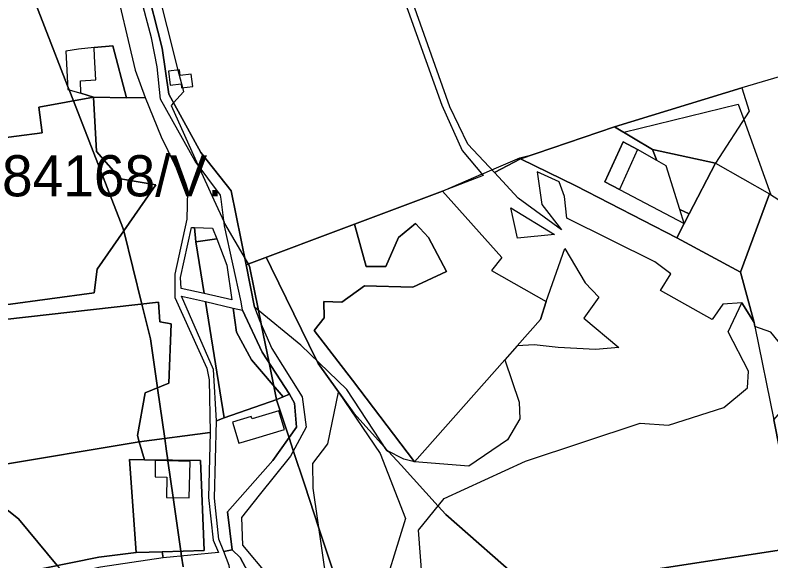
# Model space of a CAD drawing. Extents: x -477304 to -465429, y -1159113 to -1149210.
# Drawn here: x -475362.8 to -475087.6, y -1151434.9 to -1151236.1 of the extents above; entities that cross this region are included whole.
import ezdxf

# ---------------------------------------------------------------- set-up
doc = ezdxf.new("R2010")
doc.units = 0
for name, color, linetype in [('BPEJ_s', 7, 'Continuous'), ('orna_s', 7, 'Continuous'), ('PUPFL_s', 7, 'Continuous'), ('trav_porost_s', 7, 'Continuous'), ('voda_s', 7, 'Continuous'), ('zahrada_s', 7, 'Continuous')]:
    doc.layers.add(name, color=color, linetype=linetype)

msp = doc.modelspace()

# ---------------------------------------------------------------- linework, layer by layer
at = {"layer": 'BPEJ_s'}
for points in [[(-475316, -1151185), (-475320, -1151190.5), (-475319.61, -1151192.03), (-475319.27, -1151192.74), (-475319.41, -1151192.82), (-475303.49, -1151256.09), (-475301.89, -1151262.47), (-475301.5, -1151264), (-475305.1, -1151267.99), (-475306, -1151269), (-475296.2, -1151290.62), (-475290.42, -1151303.35), (-475286.72, -1151311.52), (-475286.5, -1151312), (-475279.08, -1151324.78), (-475277.96, -1151326.7)], [(-475319.41, -1151192.82), (-475303.49, -1151256.09), (-475301.89, -1151262.47), (-475301.5, -1151264), (-475305.1, -1151267.99), (-475306, -1151269), (-475296.2, -1151290.62), (-475290.42, -1151303.35), (-475286.72, -1151311.52), (-475286.5, -1151312), (-475279.08, -1151324.78), (-475277.96, -1151326.7), (-475274.33, -1151325.34), (-475271.42, -1151324.25), (-475239.26, -1151312.16), (-475207.22, -1151300.13), (-475207.02, -1151300.05), (-475206.93, -1151300.02), (-475193, -1151294), (-475192.85, -1151293.94), (-475189.22, -1151292.38), (-475179, -1151288), (-475174.62, -1151286.93), (-475144.6, -1151276.72), (-475141.21, -1151278.73), (-475099.5, -1151268.5), (-475097.5, -1151274.05), (-475087.6, -1151301.52)], [(-475360.5, -1151218.5), (-475343.64, -1151261.78), (-475343.05, -1151263.31), (-475341.5, -1151267.29), (-475323.5, -1151313.5), (-475323.22, -1151314.64), (-475316.63, -1151341.34), (-475313.5, -1151354), (-475310.96, -1151371.78), (-475310.94, -1151371.93), (-475308.32, -1151390.23), (-475307.66, -1151394.87), (-475307.2, -1151398.12), (-475307.16, -1151398.4), (-475305.25, -1151411.77), (-475302.45, -1151431.34), (-475302.2, -1151433.11), (-475301.64, -1151437.05)], [(-475301.64, -1151437.05), (-475302.2, -1151433.11), (-475302.45, -1151431.34), (-475305.25, -1151411.77), (-475307.16, -1151398.4), (-475307.2, -1151398.12), (-475307.66, -1151394.87), (-475308.32, -1151390.23), (-475310.94, -1151371.93), (-475310.96, -1151371.78), (-475313.5, -1151354), (-475316.63, -1151341.34), (-475323.22, -1151314.64), (-475323.5, -1151313.5), (-475341.5, -1151267.29), (-475343.05, -1151263.31), (-475343.64, -1151261.78), (-475360.5, -1151218.5)], [(-475467.11, -1151228.18), (-475464, -1151238), (-475453, -1151259.5), (-475439.5, -1151293.5), (-475423.12, -1151346.01), (-475422.1, -1151349.28), (-475420.59, -1151354.12), (-475420, -1151356), (-475406.5, -1151377.5), (-475385, -1151401), (-475383.41, -1151402.25), (-475361.5, -1151419.5), (-475347.45, -1151436.58), (-475344.74, -1151439.88), (-475342.91, -1151442.1), (-475342.53, -1151442.57), (-475336, -1151450.5), (-475324.5, -1151481.5), (-475323.15, -1151506.1), (-475322.12, -1151524.82), (-475322, -1151527), (-475320.48, -1151586.18)], [(-475177, -1151443.5), (-475206, -1151418), (-475208.81, -1151414.89), (-475222.26, -1151400.04), (-475226.82, -1151395), (-475227.42, -1151394.7), (-475228.28, -1151393.39), (-475239.5, -1151381), (-475252.5, -1151363), (-475253.08, -1151361.8), (-475269.5, -1151328), (-475271.42, -1151324.25), (-475239.26, -1151312.16), (-475207.22, -1151300.13), (-475207.02, -1151300.05), (-475206.93, -1151300.02), (-475193, -1151294), (-475192.85, -1151293.94), (-475189.22, -1151292.38), (-475179, -1151288), (-475174.62, -1151286.93), (-475144.6, -1151276.72), (-475141.21, -1151278.73), (-475099.5, -1151268.5), (-475097.5, -1151274.05), (-475087.6, -1151301.52)], [(-475240.2, -1151459.16), (-475252.15, -1151422.98), (-475257.34, -1151407.25), (-475261.49, -1151394.7), (-475263.05, -1151389.98), (-475267.5, -1151376.5), (-475267.59, -1151376.05), (-475268.59, -1151371.17), (-475270.31, -1151362.72), (-475273.2, -1151348.59), (-475273.37, -1151347.74), (-475274.21, -1151343.61), (-475277.5, -1151327.5), (-475277.96, -1151326.7), (-475274.33, -1151325.34), (-475271.42, -1151324.25), (-475269.5, -1151328), (-475253.08, -1151361.8), (-475252.5, -1151363), (-475239.5, -1151381), (-475228.28, -1151393.39), (-475227.42, -1151394.7), (-475226.82, -1151395), (-475222.26, -1151400.04), (-475208.81, -1151414.89), (-475206, -1151418), (-475177, -1151443.5)], [(-475277.96, -1151326.7), (-475277.5, -1151327.5), (-475274.21, -1151343.61), (-475273.37, -1151347.74), (-475273.2, -1151348.59), (-475270.31, -1151362.72), (-475268.59, -1151371.17), (-475267.59, -1151376.05), (-475267.5, -1151376.5), (-475263.05, -1151389.98), (-475261.49, -1151394.7), (-475257.34, -1151407.25), (-475252.15, -1151422.98), (-475240.2, -1151459.16), (-475238.08, -1151465.59), (-475232.8, -1151481.59), (-475232, -1151484), (-475231.23, -1151485.92), (-475231.05, -1151486.36), (-475228.17, -1151493.53), (-475223.19, -1151505.95), (-475219.83, -1151514.34), (-475214.29, -1151528.13), (-475168, -1151643.5)], [(-475347.45, -1151436.58), (-475361.5, -1151419.5), (-475383.41, -1151402.25)]]:
    msp.add_lwpolyline(points, dxfattribs=at)
at = {"layer": 'orna_s'}
for points in [[(-475144.6, -1151276.72), (-475130.68, -1151284.96), (-475129.18, -1151289.02), (-475136.14, -1151285), (-475141.43, -1151282.22), (-475148.06, -1151296.77), (-475142.77, -1151299.55), (-475119.19, -1151311.96), (-475121.9, -1151317.2), (-475158.68, -1151298.26), (-475178.84, -1151288.36)], [(-475142.77, -1151299.55), (-475148.06, -1151296.77), (-475141.43, -1151282.22), (-475136.14, -1151285)], [(-475121.9, -1151317.2), (-475119.19, -1151311.96), (-475117.35, -1151308.41), (-475107.85, -1151290.01), (-475088.14, -1151301.17), (-475088.52, -1151302.19), (-475098.68, -1151329.69)], [(-475117.35, -1151308.41), (-475119.19, -1151311.96), (-475120.79, -1151306.87)]]:
    msp.add_lwpolyline(points, close=True, dxfattribs=at)
at = {"layer": 'PUPFL_s'}
for points in [[(-475222.58, -1151226.41), (-475207.45, -1151268.85), (-475200.06, -1151285.37), (-475192.41, -1151294.46), (-475207.23, -1151300.13), (-475239.26, -1151312.16), (-475278.64, -1151326.96), (-475284.08, -1151300.07), (-475295.21, -1151286.12), (-475306.8, -1151264.87), (-475309.25, -1151248.07), (-475315.45, -1151223.69)], [(-475060.36, -1151226.55), (-475056.29, -1151250.13), (-475098.2, -1151262.5)], [(-475098.2, -1151262.5), (-475144.6, -1151276.72), (-475178.84, -1151288.36), (-475188.29, -1151293.38), (-475197.96, -1151283.06), (-475204.53, -1151269.52), (-475217.84, -1151231.85)]]:
    msp.add_lwpolyline(points, dxfattribs=at)
for points in [[(-475306.33, -1151261.58), (-475302.31, -1151261.1), (-475302.14, -1151262.5), (-475298.09, -1151262.02), (-475298.62, -1151257.54), (-475302.67, -1151258.02), (-475302.91, -1151256.02), (-475306.93, -1151256.5)], [(-475144.6, -1151276.72), (-475098.2, -1151262.5), (-475095.53, -1151271.01), (-475107.85, -1151290.01), (-475130.68, -1151284.96)], [(-475107.85, -1151290.01), (-475117.35, -1151308.41), (-475120.79, -1151306.87), (-475125.79, -1151290.97), (-475129.18, -1151289.02), (-475130.68, -1151284.96)]]:
    msp.add_lwpolyline(points, close=True, dxfattribs=at)
at = {"layer": 'trav_porost_s'}
for points in [[(-475327.19, -1151221.56), (-475319.03, -1151256.07), (-475315.39, -1151266.03), (-475322.21, -1151266.21), (-475327.22, -1151247.21), (-475333.99, -1151247.87), (-475339.71, -1151248.42), (-475344.3, -1151249.25), (-475343.57, -1151263.17), (-475338.8, -1151264.47), (-475334.26, -1151265.95), (-475354.17, -1151269.63), (-475352.88, -1151278.94), (-475381.03, -1151282.62), (-475398.8, -1151287.68), (-475397.99, -1151317.33), (-475409.39, -1151326.58), (-475405.4, -1151287.64), (-475393.01, -1151254.78), (-475387.86, -1151223.42)], [(-475382.48, -1151343.76), (-475333.94, -1151337.18), (-475332.95, -1151328.61), (-475311.55, -1151297.9), (-475324.46, -1151295.73), (-475333.13, -1151285.74), (-475334.26, -1151265.95), (-475322.21, -1151266.21), (-475315.39, -1151266.03), (-475309.65, -1151280.42), (-475300, -1151300.07), (-475300.27, -1151310.34), (-475304.66, -1151330.37), (-475304.66, -1151338.89), (-475293.01, -1151364.65), (-475292.14, -1151368.96), (-475291.73, -1151388.05), (-475317.58, -1151391.45), (-475318.25, -1151389.13), (-475315.44, -1151373.63), (-475306.77, -1151370.06), (-475305.94, -1151348.56), (-475310.06, -1151347.79), (-475310.55, -1151340.65), (-475382.73, -1151348.8)]]:
    msp.add_lwpolyline(points, dxfattribs=at)
for points in [[(-475332.95, -1151328.61), (-475333.94, -1151337.18), (-475382.48, -1151343.76), (-475385.97, -1151324.48), (-475397.99, -1151317.33), (-475398.8, -1151287.68), (-475381.03, -1151282.62), (-475352.88, -1151278.94), (-475354.17, -1151269.63), (-475334.26, -1151265.95), (-475333.13, -1151285.74), (-475324.46, -1151295.73), (-475311.55, -1151297.9)], [(-475124.07, -1151330.25), (-475129.87, -1151325.94), (-475161.9, -1151310.08), (-475162.82, -1151302.08), (-475164.72, -1151296.74), (-475172.77, -1151293.2), (-475171.08, -1151305.1), (-475163.91, -1151314.26), (-475179.6, -1151302.77), (-475188.29, -1151293.38), (-475178.84, -1151288.36), (-475158.68, -1151298.26), (-475121.9, -1151317.2), (-475098.68, -1151329.69), (-475093.77, -1151348.04), (-475098.18, -1151340.89), (-475105.1, -1151341.38), (-475109.02, -1151346.92), (-475127.8, -1151336.38)], [(-475207.23, -1151300.13), (-475185.53, -1151324.37), (-475189.37, -1151329.11), (-475169.4, -1151340.39), (-475171.52, -1151346.95), (-475180.03, -1151356.57), (-475184.54, -1151361.66), (-475217.42, -1151398.83), (-475239.96, -1151369.07), (-475253.89, -1151350.95), (-475250.3, -1151346.33), (-475250.44, -1151340.43), (-475243.85, -1151340.66), (-475235.53, -1151334.68), (-475217.93, -1151335.1), (-475205.71, -1151329.48), (-475212.29, -1151317.03), (-475217.02, -1151311.98), (-475223.18, -1151317.11), (-475227.78, -1151327.68), (-475235.01, -1151327.68), (-475239.26, -1151312.16)], [(-475068.11, -1151344.11), (-475078.67, -1151400.58), (-475078.27, -1151403.96), (-475082.26, -1151405.02), (-475086.62, -1151383.42), (-475079.05, -1151374.83), (-475080.8, -1151360), (-475087.6, -1151351.55), (-475093.48, -1151349.48), (-475093.77, -1151348.04), (-475098.68, -1151329.69), (-475088.52, -1151302.19), (-475088.14, -1151301.17), (-475084.79, -1151303.35)], [(-475179.83, -1151317.32), (-475182.36, -1151306.31), (-475166.39, -1151315.96)], [(-475302.33, -1151335.62), (-475302.53, -1151331.63), (-475298.59, -1151313.42), (-475297.48, -1151313.37), (-475296.94, -1151318.66), (-475293.93, -1151337.49)], [(-475297.48, -1151313.37), (-475290.86, -1151313.64), (-475289.39, -1151317.52), (-475296.94, -1151318.66)], [(-475253.89, -1151350.95), (-475239.96, -1151369.07), (-475217.42, -1151398.83), (-475221.22, -1151397.83), (-475227.42, -1151394.7), (-475242.07, -1151372.45), (-475258.76, -1151356.31), (-475275.67, -1151342.41), (-475278.64, -1151326.96), (-475239.26, -1151312.16), (-475235.01, -1151327.68), (-475227.78, -1151327.68), (-475223.18, -1151317.11), (-475217.02, -1151311.98), (-475212.29, -1151317.03), (-475205.71, -1151329.48), (-475217.93, -1151335.1), (-475235.53, -1151334.68), (-475243.85, -1151340.66), (-475250.44, -1151340.43), (-475250.3, -1151346.33)], [(-475296.94, -1151318.66), (-475289.39, -1151317.52), (-475285.71, -1151327.19), (-475283.87, -1151339.74), (-475293.93, -1151337.49)], [(-475171.52, -1151346.95), (-475169.4, -1151340.39), (-475162.64, -1151321.12), (-475155.3, -1151333.56), (-475150.33, -1151338.79), (-475155.73, -1151346.46), (-475143, -1151357.08), (-475151.51, -1151357.85), (-475165.05, -1151357.13), (-475173.82, -1151356.16), (-475180.03, -1151356.57)], [(-475315.44, -1151373.63), (-475318.25, -1151389.13), (-475317.58, -1151391.45), (-475371.44, -1151400.47), (-475438.93, -1151410.52), (-475438.17, -1151402.98), (-475430.65, -1151390.8), (-475422.93, -1151356.47), (-475396.94, -1151330.45), (-475393.21, -1151344.77), (-475382.73, -1151348.8), (-475310.55, -1151340.65), (-475310.06, -1151347.79), (-475305.94, -1151348.56), (-475306.77, -1151370.06)], [(-475286.71, -1151382.7), (-475289.5, -1151383.79), (-475290.53, -1151365.11), (-475302.14, -1151338.47), (-475293.46, -1151340.41)], [(-475286.71, -1151382.7), (-475293.46, -1151340.41), (-475283.43, -1151342.77), (-475282.15, -1151351.53), (-475276.76, -1151361.65), (-475265.24, -1151375.07), (-475267.55, -1151376.04)], [(-475077.46, -1151429.88), (-475130.42, -1151438.02), (-475153.01, -1151444.89), (-475179.97, -1151451.76), (-475213.34, -1151457.24), (-475215.93, -1151423.64), (-475206.57, -1151412.14), (-475177, -1151398.54), (-475135.17, -1151384.64), (-475124.91, -1151385.36), (-475104.73, -1151378.99), (-475096.15, -1151371.76), (-475095.79, -1151365.7), (-475103.16, -1151351.41), (-475098.18, -1151340.89), (-475093.77, -1151348.04), (-475093.48, -1151349.48), (-475086.62, -1151383.42), (-475082.26, -1151405.02)], [(-475217.42, -1151398.83), (-475184.54, -1151361.66), (-475179.24, -1151377.07), (-475179.03, -1151383.07), (-475183.52, -1151390.75), (-475197.57, -1151400.39)], [(-475265.24, -1151375.07), (-475262.91, -1151374.09), (-475261.05, -1151377.41), (-475260.35, -1151386.17), (-475268.89, -1151398.24), (-475285.5, -1151417.01), (-475283.71, -1151430.8), (-475286.77, -1151431.44), (-475288.55, -1151427), (-475290.23, -1151412.02), (-475289.5, -1151383.79), (-475286.71, -1151382.7), (-475267.55, -1151376.04)], [(-475250.51, -1151442.81), (-475249.32, -1151442.85), (-475254.23, -1151408.39), (-475254.33, -1151399.34), (-475248.97, -1151392.21), (-475245.1, -1151373.38), (-475229.93, -1151395.77), (-475220.67, -1151419.38), (-475230.54, -1151451.19), (-475231.11, -1151458.51), (-475247.56, -1151459.68), (-475247.78, -1151452.17)], [(-475275.1, -1151390.11), (-475264.7, -1151386.95), (-475266.82, -1151380.15), (-475276.52, -1151383.15), (-475276.83, -1151382.21), (-475283.61, -1151384.31), (-475281.27, -1151391.98)], [(-475309.21, -1151431.54), (-475293.99, -1151431.1), (-475295.25, -1151398.31), (-475315.68, -1151397.99), (-475317.58, -1151391.45), (-475291.73, -1151388.05), (-475292.4, -1151411.71), (-475290.63, -1151427.33), (-475288.73, -1151431.74), (-475308.84, -1151433.78)], [(-475399.44, -1151446.34), (-475436.11, -1151452.7), (-475444.88, -1151453.58), (-475438.93, -1151410.52), (-475371.44, -1151400.47), (-475317.58, -1151391.45), (-475315.68, -1151397.99), (-475321.07, -1151397.9), (-475318.71, -1151431.82), (-475332.35, -1151433.51), (-475372, -1151441.57)], [(-475293.99, -1151431.1), (-475309.21, -1151431.54), (-475318.71, -1151431.82), (-475321.07, -1151397.9), (-475315.68, -1151397.99), (-475295.25, -1151398.31)], [(-475299.04, -1151398.6), (-475311.73, -1151398.28), (-475311.84, -1151404.18), (-475307.54, -1151404.32), (-475307.72, -1151411.71), (-475299.37, -1151411.91)], [(-475436.11, -1151452.7), (-475399.44, -1151446.34), (-475372, -1151441.57), (-475332.35, -1151433.51), (-475318.71, -1151431.82), (-475309.21, -1151431.54), (-475308.84, -1151433.78), (-475331.74, -1151437.11), (-475342.87, -1151439.51), (-475379.85, -1151446.74), (-475400.21, -1151449.82), (-475431.55, -1151456.29), (-475451.66, -1151457.67), (-475451.6, -1151452.69), (-475450.09, -1151432.61), (-475444.93, -1151411.47), (-475438.93, -1151410.52), (-475444.88, -1151453.58)], [(-475044.87, -1151426.5), (-475045.62, -1151438.12), (-475058.02, -1151471.95), (-475056.69, -1151493.84), (-475058.02, -1151521.33), (-475064.36, -1151534.34), (-475069.84, -1151554.07), (-475067.71, -1151555.4), (-475067.25, -1151564.77), (-475063.07, -1151577.82), (-475078.19, -1151575.23), (-475096.77, -1151567.79), (-475117.78, -1151552.71), (-475129.54, -1151539.49), (-475124.55, -1151532.51), (-475106.26, -1151522.6), (-475108.24, -1151512.04), (-475119.75, -1151497.09), (-475121.74, -1151498.23), (-475125.21, -1151487.9), (-475130.42, -1151438.02), (-475077.46, -1151429.88), (-475057.18, -1151427.79)], [(-475283.71, -1151430.8), (-475280.85, -1151433.65), (-475276.2, -1151442.26), (-475274.23, -1151450.78), (-475273.59, -1151459.88), (-475273.74, -1151480.65), (-475275.79, -1151486.4), (-475275.55, -1151496.95), (-475283.1, -1151501.05), (-475287.49, -1151493.09), (-475282.99, -1151475.33), (-475276.85, -1151475.13), (-475276.64, -1151460.07), (-475274.81, -1151459.96), (-475275.38, -1151450.78), (-475281.68, -1151451.17), (-475281.11, -1151460.35), (-475284.83, -1151436.57), (-475286.77, -1151431.44)]]:
    msp.add_lwpolyline(points, close=True, dxfattribs=at)
at = {"layer": 'voda_s'}
for points in [[(-475276.2, -1151442.26), (-475280.85, -1151433.65), (-475283.71, -1151430.8), (-475285.5, -1151417.01), (-475268.89, -1151398.24), (-475260.35, -1151386.17), (-475261.05, -1151377.41), (-475262.91, -1151374.09), (-475272.83, -1151358.85), (-475279.96, -1151343.59), (-475280.42, -1151340.51), (-475286.57, -1151312.76), (-475287.72, -1151303.11), (-475287.96, -1151301.66), (-475297.21, -1151289.26), (-475309.86, -1151266.64), (-475311.08, -1151254.87), (-475313.08, -1151244.35), (-475322.62, -1151208.63)], [(-475315.45, -1151223.69), (-475309.25, -1151248.07), (-475306.8, -1151264.87), (-475295.21, -1151286.12), (-475284.08, -1151300.07), (-475278.64, -1151326.96), (-475275.67, -1151342.41), (-475273.68, -1151347.49), (-475269.31, -1151357.44), (-475258.22, -1151375.15), (-475256.82, -1151386.1), (-475262.56, -1151396.67), (-475273.92, -1151410.95), (-475280.35, -1151419.03), (-475280.04, -1151429.18), (-475270.66, -1151440.32)]]:
    msp.add_lwpolyline(points, dxfattribs=at)
msp.add_lwpolyline([(-475279.96, -1151343.59), (-475272.83, -1151358.85), (-475262.91, -1151374.09), (-475265.24, -1151375.07), (-475276.76, -1151361.65), (-475282.15, -1151351.53), (-475283.43, -1151342.77)], close=True, dxfattribs=at)
at = {"layer": 'zahrada_s'}
msp.add_lwpolyline([(-475327.22, -1151247.21), (-475322.21, -1151266.21), (-475334.26, -1151265.95), (-475338.8, -1151264.47), (-475339.02, -1151259.96), (-475333.4, -1151259.68), (-475333.83, -1151251.09), (-475333.99, -1151247.87)], close=True, dxfattribs=at)

# ---------------------------------------------------------------- texts
at = {"layer": 'BPEJ_s'}
msp.add_text('84168/V.', height=15, dxfattribs=at).set_placement((-475367.55, -1151302.08))

doc.saveas('drawing.dxf')
